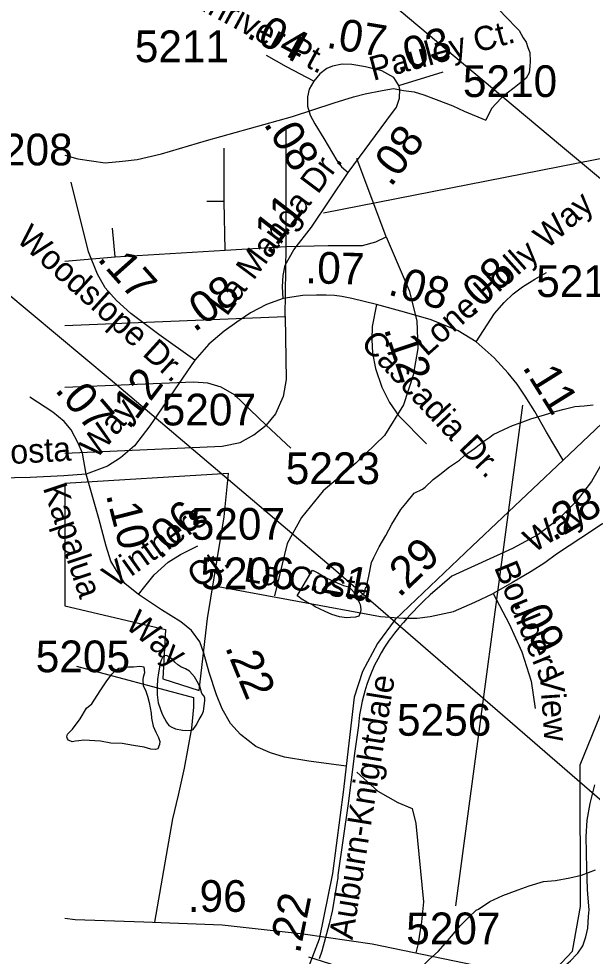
# Model space of a CAD drawing. Extents: x 2169602 to 2449496, y 721995 to 810662.
# Drawn here: x 2381932 to 2384193, y 782129 to 785825 of the extents above; entities that cross this region are included whole.
import ezdxf

# ---------------------------------------------------------------- set-up
doc = ezdxf.new("R2010")
doc.units = 0
doc.layers.add('Default', color=7, linetype='Continuous')

msp = doc.modelspace()

# ---------------------------------------------------------------- linework, layer by layer
at = {"layer": 'Default'}
for p, q in [((2383133.9, 785059.8), (2384570.3, 785341.7)), ((2383918.2, 784301.9), (2383653.8, 782327.9)), ((2382114, 783992.9), (2382114, 783510.5)), ((2382114, 783992.9), (2382114, 783510.5)), ((2382159.4, 783273), (2382621.1, 783148.5))]:
    msp.add_line(p, q, dxfattribs=at)
for points in [[(2382708.7, 786466), (2383030.3, 786197.9), (2383840.4, 785517.6)], [(2383644.1, 786039.2), (2383705.2, 785988.9), (2383783.4, 785909.4), (2383845.7, 785839.5), (2383904.1, 785777.9), (2383920.1, 785750), (2383932.1, 785731.9), (2383938.3, 785712), (2383946.3, 785692.1), (2383948.4, 785658), (2383946.6, 785636.1), (2383944.7, 785612.1), (2383932.8, 785589.9), (2383910.9, 785574), (2383885.1, 785551.9), (2383857, 785531.7), (2383840.4, 785517.6)], [(2383094.6, 785579.1), (2382987.1, 785635.1), (2382908.7, 785679.9)], [(2383430.4, 785561.2), (2383410.3, 785592.6), (2383363.2, 785619.4), (2383298.3, 785635.1), (2383244.6, 785644.1), (2383206.5, 785646.3), (2383168.5, 785637.4), (2383146.1, 785628.4), (2383119.2, 785608.2), (2383094.6, 785579.1)], [(2383430.4, 785561.2), (2383605, 785615)], [(2383094.6, 785579.1), (2383076.7, 785547.8), (2383069.9, 785516.4), (2383069.9, 785480.6), (2383081.1, 785444.7), (2383099, 785411.1), (2383134.9, 785352.9), (2383186.4, 785265.5), (2383204.3, 785240.8), (2383231.1, 785218.4)], [(2382114, 785287.2), (2382164.7, 785272.5), (2382218.7, 785264.6), (2382272.8, 785256.9), (2382340.7, 785263.1), (2382398.6, 785269.5), (2382494.5, 785291.7), (2382672.3, 785344.5), (2383011.6, 785440), (2383175.5, 785492.8), (2383251.4, 785517.1), (2383297.2, 785529.3), (2383365.1, 785541.5), (2383409.1, 785549.8), (2383449.1, 785542), (2383491.2, 785536.2), (2383529.1, 785524.4), (2383577.4, 785506.4), (2383643.4, 785480.9), (2383687.4, 785461), (2383773.5, 785425.4)], [(2383231.1, 785218.4), (2383383.4, 785424.5), (2383421.5, 785476.1), (2383432.6, 785511.9), (2383434.9, 785547.8), (2383430.4, 785561.2)], [(2383840.4, 785517.6), (2383833.2, 785511.6), (2383795.4, 785471.6), (2383773.5, 785425.4)], [(2383840.4, 785517.6), (2384067.8, 785326.6), (2384787.5, 784725.4)], [(2382985.9, 784927.1), (2382985.9, 785397.6)], [(2382741.5, 785104), (2382741.5, 785314.8)], [(2383380.8, 784964.8), (2383264.3, 785273.4)], [(2382974.5, 784722.5), (2382971.4, 784768.1), (2382973.7, 784812.9), (2382982.6, 784853.3), (2383016.2, 784913.8), (2383085.6, 785003.4), (2383231.1, 785218.4)], [(2382626.6, 784478.4), (2382484.1, 784579.9), (2382374.4, 784662.2), (2382316.8, 784714.3), (2382273, 784763.7), (2382242.8, 784818.5), (2382207.2, 784906.3), (2382139.2, 785180.7)], [(2382741.5, 785104), (2382673.8, 785104)], [(2382745.2, 784912.1), (2382741.5, 785104)], [(2382312.7, 784885.7), (2382301.4, 784998.6)], [(2383380.8, 784964.8), (2383471.1, 784754), (2383501.2, 784633.6), (2383505, 784524.4), (2383486.2, 784419.1), (2383448.5, 784302.4), (2383373.3, 784182), (2383260.5, 784072.8), (2383132.6, 783963.7), (2383046.1, 783858.3), (2382989.7, 783756.7), (2382940.8, 783549.7)], [(2382985.9, 784927.1), (2383151.4, 784930.9), (2383286.8, 784930.9), (2383339.5, 784946), (2383380.8, 784964.8)], [(2382312.7, 784885.7), (2382745.2, 784912.1)], [(2382745.2, 784912.1), (2382985.9, 784927.1)], [(2382982.2, 784651.3), (2382985.9, 784927.1)], [(2382114, 784869.6), (2382312.7, 784885.7)], [(2381771.6, 784838.2), (2382292.3, 784403.3), (2382758.2, 784008.7)], [(2383735.8, 784550.5), (2383807.7, 784662.2), (2383845.5, 784705.8), (2383881.5, 784739.9), (2383917.4, 784768.3), (2383966.6, 784798.6), (2384012.8, 784824.3)], [(2382114, 778197.9), (2382188.8, 778566.6), (2382234.9, 779658), (2382341, 780042.9), (2382465, 780302.8), (2382721.9, 780668.2), (2383036.9, 780943.9), (2383187, 781036), (2383285, 781411.2), (2383425.9, 781621.6), (2383799.9, 781748.5), (2383941, 781965.4), (2384114.9, 782148.8), (2384146.8, 782325.3), (2384145, 782883), (2384350.9, 783390.6), (2384391.9, 783642.3), (2384422, 784268.3), (2384496, 784450.5), (2384679, 784650.1), (2384787.5, 784725.4)], [(2383342.2, 784698.2), (2383245.4, 784721.5), (2383205.2, 784729.5), (2383176.8, 784733.3), (2383143.6, 784735.4), (2383106.1, 784735.4), (2383051.4, 784734.4), (2382974.5, 784722.5)], [(2382974.5, 784722.5), (2382909, 784697.8), (2382846, 784664.9), (2382791.1, 784629.3), (2382741.8, 784593.6), (2382681.5, 784541.5), (2382626.6, 784478.4)], [(2383342.2, 784698.2), (2383325.2, 784611.1), (2383323.3, 784560), (2383327.1, 784507), (2383338.4, 784446.4), (2383363, 784372.6), (2383393.3, 784312), (2383429.3, 784260.9), (2383539, 784149.2)], [(2383735.8, 784550.5), (2383663.9, 784594.1), (2383557.9, 784637.6), (2383452, 784667.9), (2383342.2, 784698.2)], [(2382114, 784616.1), (2382982.2, 784651.3)], [(2382982.2, 784651.3), (2382985.9, 784402.9), (2382974.7, 784335.1), (2382944.6, 784267.4), (2382907, 784222.2)], [(2384078, 784084.6), (2384012.1, 784194.6), (2383966.6, 784276), (2383928.8, 784336.6), (2383896.6, 784383.9), (2383860.7, 784427.5), (2383805.8, 784488.1), (2383735.8, 784550.5)], [(2384561.9, 784542.7), (2384078, 784084.6)], [(2382626.6, 784478.4), (2382448.4, 784220.5), (2382388.1, 784141), (2382333.3, 784094.3), (2382281.2, 784061.4), (2382198, 784029.7)], [(2382907, 784222.2), (2382782.8, 784342.7), (2382730.2, 784372.8), (2382677.5, 784387.8), (2382621.1, 784391.6), (2382114, 784370.7)], [(2382198, 784029.7), (2382183.1, 784111.7), (2382166.8, 784151.2), (2382138.9, 784204.7), (2382111, 784237.3), (2382066.9, 784274.5), (2381976.2, 784332.6)], [(2383265.7, 783543), (2383291.8, 783557.3), (2383299.4, 783579.3), (2383303.7, 783587.2), (2383307.2, 783603.3), (2383311.7, 783627.4), (2383323.1, 783681.6), (2383331.1, 783701.4), (2383352.5, 783743.3), (2383378.7, 783787.5), (2383402.5, 783831.8), (2383438.2, 783889.7), (2383457.9, 783913.9), (2383490.1, 783954.1), (2383523.9, 783970), (2383533.7, 783978.3), (2383565.9, 784008.3), (2383591.8, 784028.3), (2383629.5, 784058.7), (2383669.1, 784084.7), (2383689.2, 784102.8), (2383729.2, 784130.9), (2383765.2, 784159.1), (2383788.8, 784175.4), (2383802.8, 784185.4), (2383844.8, 784205.4), (2383878.4, 784221.8), (2383908.2, 784231.9), (2383950.4, 784247.8), (2384004.5, 784264), (2384046.2, 784276.3), (2384082.3, 784286.3), (2384124.3, 784296.6), (2384160.4, 784298.8), (2384196.3, 784302.7)], [(2382114, 784112.5), (2382734, 784139.4), (2382805.4, 784154.5), (2382858.1, 784184.6), (2382907, 784222.2)], [(2382907, 784222.2), (2383004.7, 784131.9)], [(2384240.4, 784087.1), (2384189.4, 784000.9), (2384129.7, 783921.1), (2384057.9, 783850.9), (2383977.9, 783790.8), (2383877.9, 783736.1), (2383639.7, 783626.8), (2383553.4, 783553.7), (2383528.9, 783530.1), (2383516.7, 783518), (2383474.9, 783474.6), (2383463.7, 783462.1), (2383448.9, 783445.3), (2383435.4, 783429.6), (2383413.7, 783402.9), (2383397.2, 783381.7), (2383392.7, 783375.1), (2383389.4, 783370.6), (2383374.2, 783347.9), (2383360.2, 783324.6), (2383346.9, 783300.7), (2383334.7, 783276.3), (2383323.4, 783251.3), (2383313.2, 783225.9), (2383303.9, 783200.1), (2383295.7, 783174.4), (2383285.7, 783134.5), (2383280.2, 783107.6), (2383275.9, 783081), (2383272.7, 783053.8), (2383271.4, 783038.4), (2383255.9, 782928.9), (2383231.2, 782731.1), (2383190.4, 782448.1), (2383189.2, 782438.1), (2383186.4, 782417.5), (2383172.9, 782337.1), (2383166.9, 782307.2), (2383155.7, 782257.4), (2383145.7, 782217.8), (2383131.9, 782168.6), (2383126.4, 782148.6), (2383116.9, 782118.9)], [(2384240.4, 784087.1), (2384189.4, 784000.9), (2384129.7, 783921.1), (2384057.9, 783850.9), (2383977.9, 783790.8), (2383877.9, 783736.1), (2383639.7, 783626.8), (2383553.4, 783553.7), (2383528.9, 783530.1), (2383516.7, 783518), (2383474.9, 783474.6), (2383463.7, 783462.1), (2383448.9, 783445.3), (2383435.4, 783429.6), (2383413.7, 783402.9), (2383397.2, 783381.7), (2383392.7, 783375.1), (2383389.4, 783370.6), (2383374.2, 783347.9), (2383360.2, 783324.6), (2383346.9, 783300.7), (2383334.7, 783276.3), (2383323.4, 783251.3), (2383313.2, 783225.9), (2383303.9, 783200.1), (2383295.7, 783174.4), (2383285.7, 783134.5), (2383280.2, 783107.6), (2383275.9, 783081), (2383272.7, 783053.8), (2383271.4, 783038.4), (2383255.9, 782928.9), (2383231.2, 782731.1), (2383190.4, 782448.1), (2383189.2, 782438.1), (2383186.4, 782417.5), (2383172.9, 782337.1), (2383166.9, 782307.2), (2383155.7, 782257.4), (2383145.7, 782217.8), (2383131.9, 782168.6), (2383126.4, 782148.6), (2383116.9, 782118.9)], [(2384078, 784084.6), (2383719.9, 783745.7), (2383415.4, 783456.7), (2383346.3, 783362.4), (2383286.7, 783251.4), (2383254.8, 783149.9), (2383223, 782877.7)], [(2382198, 784029.7), (2382110, 784022.3), (2381976.9, 784016.5), (2381668.5, 784009.1), (2381470.2, 784013.5), (2381414.7, 784008.3), (2381347.9, 783995.4), (2381274.6, 783971.7), (2381215.4, 783944.6), (2381181.8, 783923.3), (2381036.2, 783826.3), (2380989.8, 783793.3), (2380936.6, 783758.3), (2380863.1, 783714.8), (2380786, 783672.1)], [(2382114, 783510.5), (2382510.5, 783417.7), (2382500.5, 783222.1), (2382643.5, 783176.9), (2382676.2, 783460.4), (2382741.5, 783861.8), (2382759, 784032.4), (2382114, 783992.9)], [(2382114, 783510.5), (2382510.5, 783417.7), (2382500.5, 783222.1), (2382643.5, 783176.9), (2382676.2, 783460.4), (2382741.5, 783861.8), (2382759, 784032.4), (2382114, 783992.9)], [(2382403.8, 783554.6), (2382350.4, 783598.7), (2382317.9, 783649.9), (2382294.6, 783687.1), (2382276, 783745.2), (2382248.1, 783854.5), (2382198, 784029.7)], [(2382758.2, 784008.7), (2383173.2, 783657.4), (2383388.7, 783470.8)], [(2385213.8, 783916.9), (2385125.9, 783909.5), (2384992.7, 783903.7), (2384684.4, 783896.3), (2384486, 783900.7), (2384430.6, 783895.4), (2384363.7, 783882.6), (2384290.5, 783858.9), (2384231.2, 783831.8), (2384197.6, 783810.4), (2384052, 783713.5), (2384005.6, 783680.5), (2383952.5, 783645.4), (2383878.9, 783601.9), (2383801.8, 783559.3)], [(2382403.8, 783554.6), (2382428.6, 783586.8), (2382466, 783632.6), (2382521.6, 783682.6), (2382570.1, 783713.1), (2382638.1, 783746.5)], [(2383265.7, 783543), (2383269.6, 783533.1), (2383273.7, 783523.1), (2383278, 783515.2), (2383279.9, 783495.5), (2383279.7, 783487.4), (2383272.1, 783469.1), (2383260, 783465.2), (2383239.9, 783465), (2383223.9, 783463), (2383196, 783466.7), (2383165.9, 783476.6), (2383140.2, 783488.6), (2383117.9, 783498.4), (2383100.3, 783506.4), (2383090, 783514.4), (2383067.9, 783524.3), (2383045.5, 783538.2), (2383035.9, 783546.2), (2383029.7, 783549.9), (2383089.4, 783650.4), (2383111.5, 783640.6), (2383143.5, 783620.7), (2383177.4, 783604.6), (2383211.6, 783591), (2383233.5, 783585.2), (2383243.8, 783575.1), (2383253.6, 783563.1), (2383261.8, 783552.9), (2383265.7, 783543)], [(2382703.1, 783589.2), (2383358, 783469), (2383448.3, 783461.4), (2383502.8, 783461.7), (2383553.6, 783469), (2383646.3, 783488.6), (2383730, 783525.4), (2383801.8, 783559.3)], [(2383223, 782877.7), (2383075.5, 782898.1), (2382980.2, 782914.4), (2382924.4, 782930.7), (2382866.3, 782956.2), (2382806.6, 783003.6), (2382767.1, 783047), (2382733.5, 783104.3), (2382711.8, 783159.6), (2382682.7, 783247.6), (2382661.8, 783324.3), (2382645.5, 783368.5), (2382613, 783412.7), (2382571.2, 783447.6), (2382494.5, 783494.1), (2382403.8, 783554.6)], [(2383801.8, 783559.3), (2383865.8, 783438.9), (2383914.7, 783329.7), (2383952.3, 783213), (2383967.9, 783106)], [(2383388.7, 783470.8), (2384329.2, 782656.9), (2384453.4, 782544.4)], [(2382653.3, 783164.4), (2382647.2, 783188.5), (2382641, 783202.4), (2382624.8, 783230.4), (2382605.1, 783252.5), (2382588.9, 783262.2), (2382570.7, 783270.3), (2382558.8, 783278.1), (2382546.9, 783288), (2382542.8, 783293.9), (2382536.6, 783300.1), (2382526.4, 783307.8), (2382514.7, 783314), (2382504.5, 783313.9), (2382500.8, 783311.7), (2382493, 783295.8), (2382488.9, 783283.8), (2382482.9, 783245.8), (2382479, 783219.7), (2382477.4, 783191.9), (2382477.6, 783159.8), (2382481.5, 783128), (2382489.9, 783106.1), (2382497.5, 783083.8), (2382506.1, 783065.9), (2382513.9, 783052.1), (2382523.9, 783038), (2382535.8, 783032.2), (2382549.6, 783026), (2382577.9, 783020.1), (2382612.1, 783018.6), (2382619.9, 783022.3), (2382631.8, 783040.3), (2382643.7, 783062.5), (2382655.6, 783082.6), (2382659.7, 783094.6), (2382663.4, 783114.7), (2382665.4, 783136.7), (2382665.2, 783146.5), (2382663.2, 783154.4), (2382653.3, 783164.4)], [(2382219.6, 783124.6), (2382253.1, 783174.7), (2382276.8, 783210.8), (2382299.4, 783241.1), (2382313.1, 783255.2), (2382326.7, 783265), (2382346.6, 783267.2), (2382364.8, 783269.3), (2382384.9, 783269.6), (2382408.9, 783273.2), (2382418.7, 783271.3), (2382424.9, 783269.6), (2382427.2, 783245.7), (2382422.8, 783229.8), (2382421.2, 783219.5), (2382423, 783195.6), (2382431.7, 783177.7), (2382439.5, 783153.8), (2382445.8, 783129.7), (2382453.6, 783087.6), (2382455.9, 783067.8), (2382462, 783035.6), (2382472.1, 783011.8), (2382482.3, 782992), (2382488.1, 782975.7), (2382486.2, 782963.8), (2382480.3, 782946.1), (2382470.4, 782943.9), (2382452.6, 782945.8), (2382426.1, 782953.8), (2382384.3, 782959.3), (2382340, 782967.2), (2382294.5, 782968.9), (2382254.1, 782977), (2382188.1, 782980.5), (2382168.2, 782978.7), (2382156.3, 782976.4), (2382142.3, 782974.5), (2382128.4, 782980.2), (2382123.9, 782986.2), (2382121.8, 782994.2), (2382123.9, 783004.4), (2382144.4, 783024.4), (2382173.9, 783064.6), (2382199.5, 783106.5), (2382219.6, 783124.6)], [(2382621.1, 783148.5), (2382621.1, 783110.9), (2382613.6, 783028.1), (2382583.5, 782870), (2382560.9, 782764.6), (2382538.4, 782670.6), (2382466.6, 782263.6)], [(2383223, 782877.7), (2383212.4, 782786.5), (2383168.5, 782455.6), (2383116.1, 782195.9), (2383053.4, 782031.5), (2382990.6, 781902.7), (2382917.8, 781787.6)], [(2383264.3, 782855), (2383347, 782779.7), (2383426, 782734.5), (2383482.4, 782712), (2383497.4, 782651.7), (2383527.5, 782343.1), (2383520, 782264.1), (2383505, 782173.8), (2383497.8, 782142.2)], [(2383932.2, 781956.4), (2383946.1, 781976.6), (2383972.3, 782008.7), (2384000, 782032.9), (2384033.9, 782057), (2384069.9, 782079.2), (2384107.5, 782111.1), (2384131.5, 782137.2), (2384135.6, 782141.4), (2384155.5, 782169.6), (2384166.9, 782205.6), (2384175.1, 782239.7), (2384178.6, 782285.4), (2384180.9, 782311.4), (2384176.6, 782357.5), (2384174.5, 782391.5), (2384171.9, 782479.5), (2384169.8, 782531.3), (2384169.6, 782539.4), (2384169.4, 782599.5), (2384173.1, 782665.5), (2384185, 782731.4), (2384202.8, 782805.4)], [(2383073.6, 782126.8), (2383318.2, 782048.6), (2383372.2, 782036.9), (2383418.2, 782034.9), (2383456.1, 782043.2), (2383476.1, 782053.2), (2383505.9, 782073.3), (2383551.8, 782117.6), (2383585.6, 782147.7), (2383623.5, 782191.7), (2383673.1, 782250.1), (2383705, 782282.3), (2383735, 782310.2), (2383744.8, 782314.2), (2383788.6, 782344.5), (2383840.5, 782368.7), (2383900.6, 782391.1), (2383944.5, 782407.2), (2384000.2, 782423.4), (2384048.3, 782427.6), (2384104.3, 782437.9), (2384150.1, 782448.2), (2384206, 782470.2)], [(2382114, 782279.4), (2382154.6, 782273.7), (2382425.7, 782265.3), (2382733.3, 782252.7), (2383053.5, 782217.1), (2383325.5, 782177.4), (2383726.3, 782095.7), (2384069.5, 782020.3), (2384509, 781934.4), (2385405.8, 781764.8), (2385730.1, 781710.3), (2385933.7, 781674.7)]]:
    msp.add_lwpolyline(points, dxfattribs=at)

# ---------------------------------------------------------------- texts
for s, height, rotation, p in [('Sunriver Pt.', 95, 331.7216, (2382535.4, 785920)), ('.04', 125, 332.4745, (2382824.8, 785753.7)), ('.07', 125, 350.5316, (2383140.9, 785711.3)), ('Pauley Ct.', 95, 15.1996, (2383329.1, 785579.6)), ('.03', 125, 17.1122, (2383425.8, 785609.3)), ('.08', 125, 301.5926, (2382894.9, 785410.4)), ('.08', 125, 53.5469, (2383399.1, 785157.8)), ('La Manga Dr.', 95, 53.2357, (2382751.4, 784648.6)), ('Lone Holly Way', 95, 41.694, (2383539.5, 784490.4)), ('.11', 125, 52.2407, (2382920.2, 784887.8)), ('Woodslope Dr.', 95, 317.8127, (2381918.2, 784950.9)), ('.17', 125, 311.6171, (2382238.3, 784876.7)), ('.07', 125, 358.2628, (2383060.5, 784782.8)), ('.08', 125, 43.4684, (2383720.4, 784648.6)), ('.08', 125, 344.0453, (2383383.3, 784738.7)), ('.08', 125, 35.8538, (2382623.7, 784586.6)), ('Cascadia Dr.', 95, 313.2566, (2383275.7, 784542.2)), ('.12', 125, 288.425, (2383370.1, 784602.3)), ('.12', 125, 52.8312, (2382366.4, 784201.4)), ('.11', 125, 301.9904, (2383915, 784451.6)), ('.07', 125, 310.5839, (2382070.9, 784359.8)), ('Way', 95, 49.856, (2382237.4, 784085.3)), ('La Costa  ', 95, 3.2719, (2381632.8, 784054)), ('Kapalua', 95, 288.4132, (2382026.3, 783976)), ('.28', 125, 30.6071, (2384039.5, 783762.6)), ('.10', 125, 284.3144, (2382275, 783948.2)), ('.06', 125, 42.0038, (2382488.3, 783689.6)), ('Way', 95, 32.2549, (2383960.9, 783716.7)), ('Vintners', 95, 35.5489, (2382305.6, 783574.2)), ('.29', 125, 43.5048, (2383431.8, 783540.1)), ('Ct.', 95, 35.5489, (2382639.7, 783576.1)), ('La Costa  ', 95, 350.4764, (2382815.7, 783608.1)), ('.21', 125, 349.593, (2383070.9, 783574)), ('Boulders', 95, 292.2522, (2383804.6, 783662.7)), ('.09', 125, 295.1999, (2383878.3, 783523.2)), ('Way', 95, 320.1588, (2382347, 783427.8)), ('.22', 125, 292.2377, (2382744, 783347.5)), ('View', 95, 273.9665, (2383985.5, 783249)), ('Auburn-Knightdale', 95, 80.8529, (2383247.7, 782191.4)), ('.22', 125, 78.609, (2383039.8, 782135.9))]:
    msp.add_text(s, height=height, rotation=rotation, dxfattribs=at).set_placement(p)
for s, p in [('5211', (2382389.4, 785653.6)), ('5210', (2383682.7, 785516.2)), ('5208', (2381772.9, 785246.7)), ('5212', (2383971.7, 784727.8)), ('5207', (2382495.4, 784221.6)), ('5223', (2382984.5, 783990.2)), ('5207', (2382609.9, 783770.9)), ('5206', (2382648.1, 783576)), ('5205', (2381999, 783248.6)), ('5256', (2383423, 782998.3)), ('.96', (2382598.3, 782304)), ('5207', (2383459.3, 782176.4))]:
    msp.add_text(s, height=125, dxfattribs=at).set_placement(p)

doc.saveas('drawing.dxf')
